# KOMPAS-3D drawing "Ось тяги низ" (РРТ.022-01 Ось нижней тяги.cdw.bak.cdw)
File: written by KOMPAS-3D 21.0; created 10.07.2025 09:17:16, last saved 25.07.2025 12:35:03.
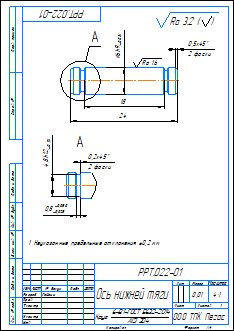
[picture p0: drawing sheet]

Sheet 1: A4, portrait

Document properties: Автор: User; Полное имя файла: C:\Users\User\Desktop\Ручной ротатор КД\Чертежи\РРТ.022-01 Ось нижней тяги.cdw.bak.cdw; Знак неуказанной шероховатости: 4; Параметр неуказанной шероховатости: Ra 3.2; Масса: 0.005156

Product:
- Part/product: Ось тяги низ
    Масса: 0.005156
    Форматы листов документа: A4

Title block, sheet 1: Наименование: Ось нижней тяги; designation: РРТ.022 - 01; Материал: Круг  6-B1-ГОСТ 5632-2014 AISI 304; Масса: 0,01; Количество листов документа: 1; organisation: ООО ТПК Пегас; Форматы листов документа: A4; stored path: C:\Users\User\Desktop\Р-й Рот-р\Компас чертежи\Ось хомута ПРС.cdw; Разработал: Гайсин

Views: Вид 1, Слева, Выносной элемент 2, Выносной элемент А, Выносной элемент
Referenced files in C:\Users\User\Desktop\Ручной ротатор Ринат\П2\: Ось ПРС.m3d
Referenced files in C:\Users\User\Desktop\Ручной ротатор КД\Модели КД\: РРТ.022-01 Ось нижней тяги.m3d, РРТ.022 Ось ТЯГИ.m3d
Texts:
  Ra 1.6
  Ось тяги низ
  Ra 3.2
  Ra 3.2 ( )
Dimensions and other numbers on the sheet: 6; 24; 0,5; 2 фаски; 18; 0,8; 4,8; 0,2; 4:1; 1; 0,01

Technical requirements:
  Неуказанные предельные отклонения  0,2 мм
